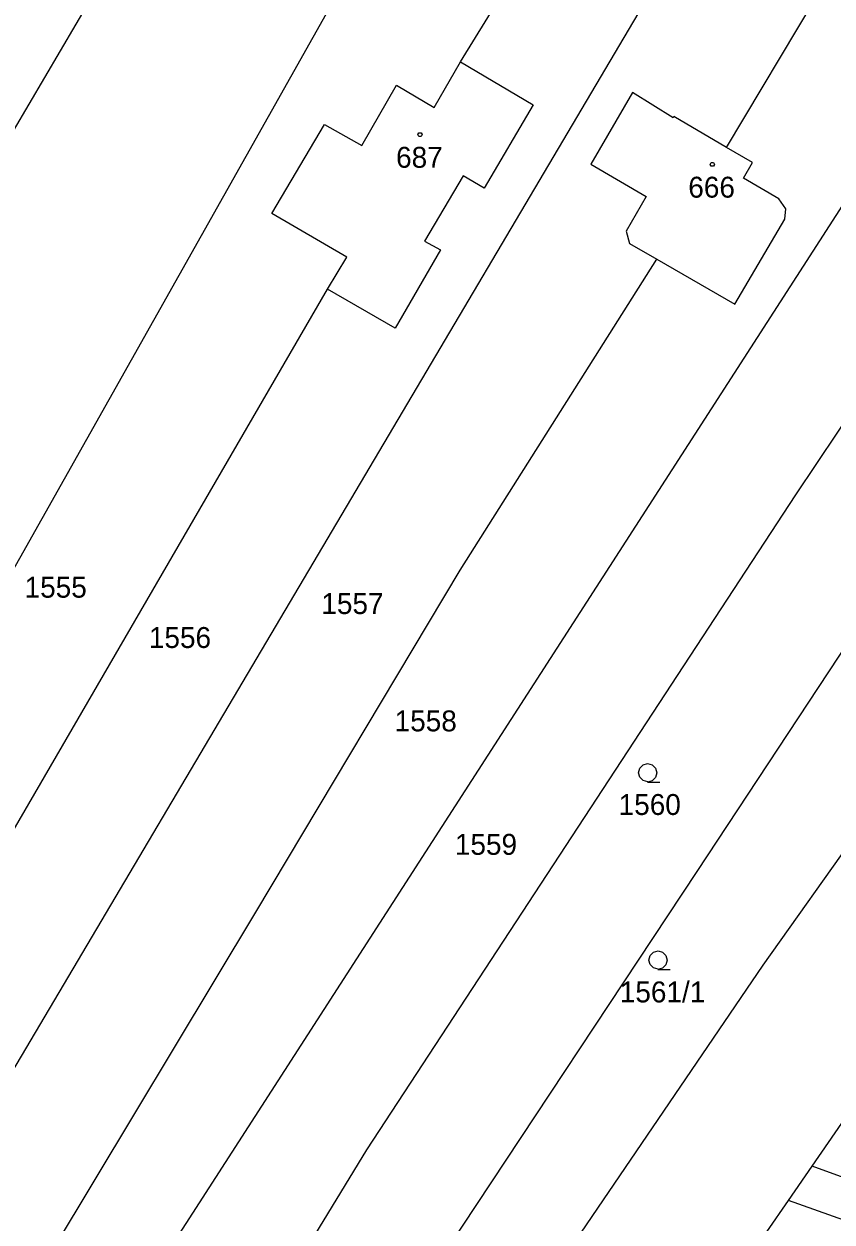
# Model space of a CAD drawing. Extents: x -580630 to -576196, y -1189024 to -1183567.
# Drawn here: x -578746.6 to -578680.9, y -1185461.5 to -1185364 of the extents above; entities that cross this region are included whole.
import ezdxf

# ---------------------------------------------------------------- set-up
doc = ezdxf.new("R2010")
doc.units = 0
for name, color, linetype in [('Vrstva 1', 7, 'Continuous'), ('Vrstva 18', 7, 'Continuous'), ('Vrstva 19', 7, 'Continuous'), ('Vrstva 25', 7, 'Continuous')]:
    doc.layers.add(name, color=color, linetype=linetype)

msp = doc.modelspace()

# ---------------------------------------------------------------- linework, layer by layer
at = {"layer": 'Vrstva 1'}
for p, q in [((-578782.68, -1185470.84), (-578717.4, -1185354.98)), ((-578737.6, -1185355.83), (-578771.13, -1185412.9)), ((-578711.12, -1185367.13), (-578705.14, -1185357.38)), ((-578694.5, -1185359.47), (-578766.11, -1185480.47)), ((-578689.49, -1185374.08), (-578682.16, -1185361.83)), ((-578670.57, -1185364.05), (-578751.46, -1185489.49)), ((-578683.86, -1185402.33), (-578659.65, -1185366.18)), ((-578713.28, -1185370.85), (-578711.12, -1185367.13)), ((-578711.12, -1185367.13), (-578705.21, -1185370.61)), ((-578719.17, -1185373.93), (-578716.34, -1185369.03)), ((-578716.34, -1185369.03), (-578713.28, -1185370.85)), ((-578697.14, -1185369.62), (-578700.53, -1185375.44)), ((-578693.83, -1185371.67), (-578697.14, -1185369.62)), ((-578705.21, -1185370.61), (-578709.2, -1185377.39)), ((-578726.48, -1185379.47), (-578722.19, -1185372.21)), ((-578722.19, -1185372.21), (-578719.17, -1185373.93)), ((-578693.78, -1185371.58), (-578693.83, -1185371.67)), ((-578689.49, -1185374.08), (-578693.78, -1185371.58)), ((-578687.39, -1185375.31), (-578689.49, -1185374.08)), ((-578688.11, -1185376.6), (-578687.39, -1185375.31)), ((-578700.53, -1185375.44), (-578696.02, -1185378.07)), ((-578710.92, -1185376.39), (-578714.05, -1185381.7)), ((-578709.2, -1185377.39), (-578710.92, -1185376.39)), ((-578685.23, -1185378.28), (-578688.11, -1185376.6)), ((-578696.02, -1185378.07), (-578697.65, -1185380.89)), ((-578684.68, -1185379.09), (-578685.23, -1185378.28)), ((-578684.75, -1185379.91), (-578684.68, -1185379.09)), ((-578720.39, -1185383.02), (-578726.48, -1185379.47)), ((-578688.82, -1185386.84), (-578684.75, -1185379.91)), ((-578697.65, -1185380.89), (-578697.39, -1185381.89)), ((-578714.05, -1185381.7), (-578712.77, -1185382.41)), ((-578697.39, -1185381.89), (-578695.16, -1185383.18)), ((-578721.94, -1185385.62), (-578720.39, -1185383.02)), ((-578712.77, -1185382.41), (-578716.45, -1185388.79)), ((-578711.15, -1185408.45), (-578695.16, -1185383.18)), ((-578695.16, -1185383.18), (-578688.82, -1185386.84)), ((-578756.92, -1185445.82), (-578721.94, -1185385.62)), ((-578716.45, -1185388.79), (-578721.94, -1185385.62)), ((-578665.59, -1185393.06), (-578691.92, -1185432.96)), ((-578686.52, -1185440.59), (-578656.95, -1185398.87)), ((-578718.74, -1185455.6), (-578683.86, -1185402.33)), ((-578727.78, -1185436.28), (-578711.15, -1185408.45)), ((-578691.92, -1185432.96), (-578735.92, -1185499.42)), ((-578757.5, -1185485.68), (-578727.78, -1185436.28)), ((-578717.23, -1185485.71), (-578686.52, -1185440.59)), ((-578682.53, -1185456.94), (-578679.33, -1185452.3)), ((-578742.96, -1185495.14), (-578718.74, -1185455.6)), ((-578684.44, -1185459.71), (-578682.53, -1185456.94)), ((-578645.95, -1185470.31), (-578682.53, -1185456.94)), ((-578686.21, -1185462.28), (-578684.44, -1185459.71)), ((-578648.61, -1185472.61), (-578684.44, -1185459.71))]:
    msp.add_line(p, q, dxfattribs=at)
at = {"layer": 'Vrstva 25'}
for points in [[(-578714.34, -1185372.89), (-578714.25, -1185373.04), (-578714.34, -1185373.19), (-578714.52, -1185373.19), (-578714.61, -1185373.04), (-578714.52, -1185372.89)], [(-578690.56, -1185375.32), (-578690.47, -1185375.47), (-578690.56, -1185375.62), (-578690.74, -1185375.62), (-578690.83, -1185375.47), (-578690.74, -1185375.32)]]:
    msp.add_lwpolyline(points, close=True, dxfattribs=at)
for points in [[(-578695.9, -1185425.67), (-578696.28, -1185425.57), (-578696.55, -1185425.3), (-578696.65, -1185424.93), (-578696.55, -1185424.56), (-578696.28, -1185424.29), (-578695.91, -1185424.19), (-578695.54, -1185424.29), (-578695.27, -1185424.56), (-578695.17, -1185424.94), (-578695.27, -1185425.32), (-578695.54, -1185425.59), (-578695.92, -1185425.69), (-578694.92, -1185425.69)], [(-578695.05, -1185440.91), (-578695.43, -1185440.81), (-578695.7, -1185440.54), (-578695.8, -1185440.17), (-578695.7, -1185439.8), (-578695.43, -1185439.53), (-578695.06, -1185439.43), (-578694.69, -1185439.53), (-578694.42, -1185439.8), (-578694.32, -1185440.18), (-578694.42, -1185440.56), (-578694.69, -1185440.83), (-578695.07, -1185440.93), (-578694.07, -1185440.93)]]:
    msp.add_lwpolyline(points, dxfattribs=at)

# ---------------------------------------------------------------- texts
at = {"layer": 'Vrstva 18'}
for s, p in [('1555', (-578746.586, -1185410.7)), ('1557', (-578722.449, -1185412.03)), ('1556', (-578736.479, -1185414.79)), ('1558', (-578716.489, -1185421.57)), ('1560', (-578698.269, -1185428.37)), ('1559', (-578711.589, -1185431.61)), ('1561/1', (-578698.175, -1185443.61))]:
    msp.add_text(s, height=1.7, dxfattribs=at).set_placement(p)
at = {"layer": 'Vrstva 19'}
for s, p in [('687', (-578716.371, -1185375.74)), ('666', (-578692.604, -1185378.17))]:
    msp.add_text(s, height=1.7, dxfattribs=at).set_placement(p)

doc.saveas('drawing.dxf')
